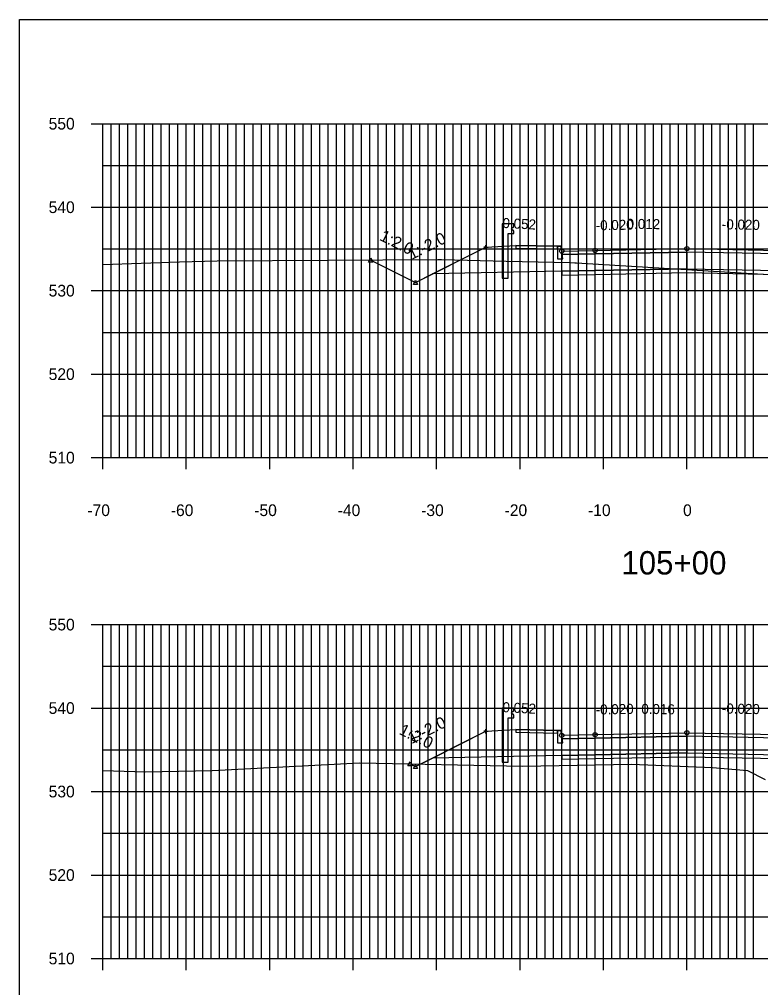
# Model space of a CAD drawing. Extents: x 1509063 to 1512863, y 401160 to 402918.
# Drawn here: x 1511822.7 to 1511911.6, y 402346.1 to 402462.1 of the extents above; entities that cross this region are included whole.
import ezdxf

# ---------------------------------------------------------------- set-up
doc = ezdxf.new("R2010")
doc.units = 0
for name, color, linetype in [('DD_P', 7, 'Continuous'), ('LCUT_P', 7, 'Continuous'), ('NBL1', 7, 'Continuous'), ('PET_P', 7, 'Continuous'), ('PRC', 7, 'Continuous'), ('PSP_P', 7, 'Continuous'), ('RBS_P', 7, 'Continuous'), ('RCC_P', 7, 'Continuous'), ('RGR_P', 7, 'Continuous'), ('XAX_P', 7, 'Continuous'), ('XAXTIC_P', 7, 'Continuous'), ('XAXTXT_P_T', 7, 'Continuous'), ('XGL_P', 7, 'Continuous'), ('XSL1_P', 7, 'Continuous'), ('XSL1_P_T', 7, 'Continuous'), ('XSL2_P', 7, 'Continuous'), ('XSL3_P', 7, 'Continuous'), ('XSLOG', 7, 'Continuous')]:
    doc.layers.add(name, color=color, linetype=linetype)

msp = doc.modelspace()

# ---------------------------------------------------------------- linework, layer by layer
at = {"layer": 'DD_P'}
for points in [[(1511864.84, 402433.25), (1511870.2, 402430.57), (1511878.65, 402434.8), (1511882.23, 402435.01)], [(1511869.55, 402372.9), (1511870.2, 402372.57), (1511878.65, 402376.8), (1511882.23, 402377.01)]]:
    msp.add_lwpolyline(points, dxfattribs=at)
for points in [[(1511870.2, 402430.82), (1511870.45, 402430.32), (1511869.95, 402430.32)], [(1511870.2, 402372.82), (1511870.45, 402372.32), (1511869.95, 402372.32)]]:
    msp.add_lwpolyline(points, close=True, dxfattribs=at)
at = {"layer": 'LCUT_P'}
for points in [[(1511864.84, 402433.5), (1511865.09, 402433), (1511864.59, 402433)], [(1511869.55, 402373.15), (1511869.8, 402372.65), (1511869.3, 402372.65)]]:
    msp.add_lwpolyline(points, close=True, dxfattribs=at)
at = {"layer": 'NBL1'}
msp.add_lwpolyline([(1512142.73, 402252.08), (1511822.73, 402252.08), (1511822.73, 402462.08), (1512142.73, 402462.08)], close=True, dxfattribs=at)
at = {"layer": 'PET_P'}
for centre in [(1511891.73, 402434.4), (1511891.73, 402376.4)]:
    msp.add_circle(centre, 0.25, dxfattribs=at)
at = {"layer": 'PRC'}
for centre in [(1511902.73, 402434.62), (1511902.73, 402376.62)]:
    msp.add_circle(centre, 0.25, dxfattribs=at)
at = {"layer": 'PSP_P'}
for centre in [(1511887.73, 402434.32), (1511887.73, 402376.32)]:
    msp.add_circle(centre, 0.25, dxfattribs=at)
at = {"layer": 'RBS_P'}
for points in [[(1511887.8, 402433.9), (1511891.73, 402433.98), (1511902.73, 402434.2), (1511902.73, 402432.2), (1511891.73, 402431.98), (1511887.8, 402431.9), (1511872.24, 402431.59), (1511878.65, 402434.8), (1511882.23, 402435.01), (1511882.23, 402434.68), (1511887.23, 402434.58), (1511887.23, 402433.41), (1511887.88, 402433.41)], [(1511902.73, 402434.2), (1511902.73, 402432.2), (1511913.73, 402431.98), (1511917.73, 402431.9), (1511928.24, 402431.69), (1511917.73, 402434.32), (1511917.73, 402433.9), (1511913.73, 402433.98)], [(1511887.8, 402375.9), (1511891.73, 402375.98), (1511902.73, 402376.2), (1511902.73, 402374.2), (1511891.73, 402373.98), (1511887.8, 402373.9), (1511872.24, 402373.59), (1511878.65, 402376.8), (1511882.23, 402377.01), (1511882.23, 402376.68), (1511887.23, 402376.58), (1511887.23, 402375.41), (1511887.88, 402375.41)], [(1511902.73, 402376.2), (1511902.73, 402374.2), (1511913.73, 402373.98), (1511917.73, 402373.9), (1511928.57, 402373.69), (1511921.31, 402376.1), (1511917.73, 402376.32), (1511917.73, 402375.9), (1511913.73, 402375.98)]]:
    msp.add_lwpolyline(points, close=True, dxfattribs=at)
for points in [[(1511878.65, 402434.8), (1511878.65, 402435.05), (1511878.65, 402434.8), (1511878.4, 402434.8), (1511878.65, 402434.8), (1511878.65, 402434.55), (1511878.65, 402434.8), (1511878.9, 402434.8)], [(1511878.65, 402376.8), (1511878.65, 402377.05), (1511878.65, 402376.8), (1511878.4, 402376.8), (1511878.65, 402376.8), (1511878.65, 402376.55), (1511878.65, 402376.8), (1511878.9, 402376.8)]]:
    msp.add_lwpolyline(points, dxfattribs=at)
at = {"layer": 'RCC_P'}
for points in [[(1511887.73, 402434.32), (1511887.63, 402434.9), (1511887.23, 402434.91), (1511887.23, 402433.41), (1511887.88, 402433.41)], [(1511887.73, 402376.32), (1511887.63, 402376.9), (1511887.23, 402376.91), (1511887.23, 402375.41), (1511887.88, 402375.41)]]:
    msp.add_lwpolyline(points, close=True, dxfattribs=at)
at = {"layer": 'RGR_P'}
for points in [[(1511881.29, 402436.41), (1511881.98, 402436.41), (1511881.98, 402436.71), (1511881.68, 402436.99), (1511881.98, 402437.28), (1511881.98, 402437.58), (1511880.6, 402437.58), (1511880.6, 402431.08), (1511881.29, 402431.08)], [(1511881.29, 402378.41), (1511881.98, 402378.41), (1511881.98, 402378.71), (1511881.68, 402378.99), (1511881.98, 402379.28), (1511881.98, 402379.58), (1511880.6, 402379.58), (1511880.6, 402373.08), (1511881.29, 402373.08)]]:
    msp.add_lwpolyline(points, close=True, dxfattribs=at)
at = {"layer": 'XAX_P'}
for p, q in [((1511832.73, 402409.58), (1511832.73, 402449.58)), ((1511902.73, 402409.58), (1511902.73, 402449.58)), ((1511832.73, 402409.58), (1511972.73, 402409.58)), ((1511832.73, 402349.58), (1511832.73, 402389.58)), ((1511902.73, 402349.58), (1511902.73, 402389.58)), ((1511832.73, 402349.58), (1511972.73, 402349.58))]:
    msp.add_line(p, q, dxfattribs=at)
at = {"layer": 'XAXTIC_P'}
for p, q in [((1511831.33, 402449.58), (1511834.13, 402449.58)), ((1511901.33, 402449.58), (1511904.13, 402449.58)), ((1511831.33, 402439.58), (1511834.13, 402439.58)), ((1511901.33, 402439.58), (1511904.13, 402439.58)), ((1511831.33, 402429.58), (1511834.13, 402429.58)), ((1511901.33, 402429.58), (1511904.13, 402429.58)), ((1511831.33, 402419.58), (1511834.13, 402419.58)), ((1511901.33, 402419.58), (1511904.13, 402419.58)), ((1511832.73, 402408.18), (1511832.73, 402410.98)), ((1511842.73, 402408.18), (1511842.73, 402410.98)), ((1511852.73, 402408.18), (1511852.73, 402410.98)), ((1511862.73, 402408.18), (1511862.73, 402410.98)), ((1511872.73, 402408.18), (1511872.73, 402410.98)), ((1511882.73, 402408.18), (1511882.73, 402410.98)), ((1511892.73, 402408.18), (1511892.73, 402410.98)), ((1511902.73, 402408.18), (1511902.73, 402410.98)), ((1511831.33, 402409.58), (1511834.13, 402409.58)), ((1511901.33, 402409.58), (1511904.13, 402409.58)), ((1511831.33, 402389.58), (1511834.13, 402389.58)), ((1511901.33, 402389.58), (1511904.13, 402389.58)), ((1511831.33, 402379.58), (1511834.13, 402379.58)), ((1511901.33, 402379.58), (1511904.13, 402379.58)), ((1511831.33, 402369.58), (1511834.13, 402369.58)), ((1511901.33, 402369.58), (1511904.13, 402369.58)), ((1511831.33, 402359.58), (1511834.13, 402359.58)), ((1511901.33, 402359.58), (1511904.13, 402359.58)), ((1511832.73, 402348.18), (1511832.73, 402350.98)), ((1511842.73, 402348.18), (1511842.73, 402350.98)), ((1511852.73, 402348.18), (1511852.73, 402350.98)), ((1511862.73, 402348.18), (1511862.73, 402350.98)), ((1511872.73, 402348.18), (1511872.73, 402350.98)), ((1511882.73, 402348.18), (1511882.73, 402350.98)), ((1511892.73, 402348.18), (1511892.73, 402350.98)), ((1511902.73, 402348.18), (1511902.73, 402350.98)), ((1511831.33, 402349.58), (1511834.13, 402349.58)), ((1511901.33, 402349.58), (1511904.13, 402349.58))]:
    msp.add_line(p, q, dxfattribs=at)
at = {"layer": 'XGL_P'}
for p, q in [((1511832.73, 402449.58), (1511972.73, 402449.58)), ((1511832.73, 402409.58), (1511832.73, 402449.58)), ((1511833.73, 402409.58), (1511833.73, 402449.58)), ((1511834.73, 402409.58), (1511834.73, 402449.58)), ((1511835.73, 402409.58), (1511835.73, 402449.58)), ((1511836.73, 402409.58), (1511836.73, 402449.58)), ((1511837.73, 402409.58), (1511837.73, 402449.58)), ((1511838.73, 402409.58), (1511838.73, 402449.58)), ((1511839.73, 402409.58), (1511839.73, 402449.58)), ((1511840.73, 402409.58), (1511840.73, 402449.58)), ((1511841.73, 402409.58), (1511841.73, 402449.58)), ((1511842.73, 402409.58), (1511842.73, 402449.58)), ((1511843.73, 402409.58), (1511843.73, 402449.58)), ((1511844.73, 402409.58), (1511844.73, 402449.58)), ((1511845.73, 402409.58), (1511845.73, 402449.58)), ((1511846.73, 402409.58), (1511846.73, 402449.58)), ((1511847.73, 402409.58), (1511847.73, 402449.58)), ((1511848.73, 402409.58), (1511848.73, 402449.58)), ((1511849.73, 402409.58), (1511849.73, 402449.58)), ((1511850.73, 402409.58), (1511850.73, 402449.58)), ((1511851.73, 402409.58), (1511851.73, 402449.58)), ((1511852.73, 402409.58), (1511852.73, 402449.58)), ((1511853.73, 402409.58), (1511853.73, 402449.58)), ((1511854.73, 402409.58), (1511854.73, 402449.58)), ((1511855.73, 402409.58), (1511855.73, 402449.58)), ((1511856.73, 402409.58), (1511856.73, 402449.58)), ((1511857.73, 402409.58), (1511857.73, 402449.58)), ((1511858.73, 402409.58), (1511858.73, 402449.58)), ((1511859.73, 402409.58), (1511859.73, 402449.58)), ((1511860.73, 402409.58), (1511860.73, 402449.58)), ((1511861.73, 402409.58), (1511861.73, 402449.58)), ((1511862.73, 402409.58), (1511862.73, 402449.58)), ((1511863.73, 402409.58), (1511863.73, 402449.58)), ((1511864.73, 402409.58), (1511864.73, 402449.58)), ((1511865.73, 402409.58), (1511865.73, 402449.58)), ((1511866.73, 402409.58), (1511866.73, 402449.58)), ((1511867.73, 402409.58), (1511867.73, 402449.58)), ((1511868.73, 402409.58), (1511868.73, 402449.58)), ((1511869.73, 402409.58), (1511869.73, 402449.58)), ((1511870.73, 402409.58), (1511870.73, 402449.58)), ((1511871.73, 402409.58), (1511871.73, 402449.58)), ((1511872.73, 402409.58), (1511872.73, 402449.58)), ((1511873.73, 402409.58), (1511873.73, 402449.58)), ((1511874.73, 402409.58), (1511874.73, 402449.58)), ((1511875.73, 402409.58), (1511875.73, 402449.58)), ((1511876.73, 402409.58), (1511876.73, 402449.58)), ((1511877.73, 402409.58), (1511877.73, 402449.58)), ((1511878.73, 402409.58), (1511878.73, 402449.58)), ((1511879.73, 402409.58), (1511879.73, 402449.58)), ((1511880.73, 402409.58), (1511880.73, 402449.58)), ((1511881.73, 402409.58), (1511881.73, 402449.58)), ((1511882.73, 402409.58), (1511882.73, 402449.58)), ((1511883.73, 402409.58), (1511883.73, 402449.58)), ((1511884.73, 402409.58), (1511884.73, 402449.58)), ((1511885.73, 402409.58), (1511885.73, 402449.58)), ((1511886.73, 402409.58), (1511886.73, 402449.58)), ((1511887.73, 402409.58), (1511887.73, 402449.58)), ((1511888.73, 402409.58), (1511888.73, 402449.58)), ((1511889.73, 402409.58), (1511889.73, 402449.58)), ((1511890.73, 402409.58), (1511890.73, 402449.58)), ((1511891.73, 402409.58), (1511891.73, 402449.58)), ((1511892.73, 402409.58), (1511892.73, 402449.58)), ((1511893.73, 402409.58), (1511893.73, 402449.58)), ((1511894.73, 402409.58), (1511894.73, 402449.58)), ((1511895.73, 402409.58), (1511895.73, 402449.58)), ((1511896.73, 402409.58), (1511896.73, 402449.58)), ((1511897.73, 402409.58), (1511897.73, 402449.58)), ((1511898.73, 402409.58), (1511898.73, 402449.58)), ((1511899.73, 402409.58), (1511899.73, 402449.58)), ((1511900.73, 402409.58), (1511900.73, 402449.58)), ((1511901.73, 402409.58), (1511901.73, 402449.58)), ((1511902.73, 402409.58), (1511902.73, 402449.58)), ((1511903.73, 402409.58), (1511903.73, 402449.58)), ((1511904.73, 402409.58), (1511904.73, 402449.58)), ((1511905.73, 402409.58), (1511905.73, 402449.58)), ((1511906.73, 402409.58), (1511906.73, 402449.58)), ((1511907.73, 402409.58), (1511907.73, 402449.58)), ((1511908.73, 402409.58), (1511908.73, 402449.58)), ((1511909.73, 402409.58), (1511909.73, 402449.58)), ((1511910.73, 402409.58), (1511910.73, 402449.58)), ((1511832.73, 402444.58), (1511972.73, 402444.58)), ((1511832.73, 402439.58), (1511972.73, 402439.58)), ((1511832.73, 402434.58), (1511972.73, 402434.58)), ((1511832.73, 402429.58), (1511972.73, 402429.58)), ((1511832.73, 402424.58), (1511972.73, 402424.58)), ((1511832.73, 402419.58), (1511972.73, 402419.58)), ((1511832.73, 402414.58), (1511972.73, 402414.58)), ((1511832.73, 402409.58), (1511972.73, 402409.58)), ((1511832.73, 402389.58), (1511972.73, 402389.58)), ((1511832.73, 402349.58), (1511832.73, 402389.58)), ((1511833.73, 402349.58), (1511833.73, 402389.58)), ((1511834.73, 402349.58), (1511834.73, 402389.58)), ((1511835.73, 402349.58), (1511835.73, 402389.58)), ((1511836.73, 402349.58), (1511836.73, 402389.58)), ((1511837.73, 402349.58), (1511837.73, 402389.58)), ((1511838.73, 402349.58), (1511838.73, 402389.58)), ((1511839.73, 402349.58), (1511839.73, 402389.58)), ((1511840.73, 402349.58), (1511840.73, 402389.58)), ((1511841.73, 402349.58), (1511841.73, 402389.58)), ((1511842.73, 402349.58), (1511842.73, 402389.58)), ((1511843.73, 402349.58), (1511843.73, 402389.58)), ((1511844.73, 402349.58), (1511844.73, 402389.58)), ((1511845.73, 402349.58), (1511845.73, 402389.58)), ((1511846.73, 402349.58), (1511846.73, 402389.58)), ((1511847.73, 402349.58), (1511847.73, 402389.58)), ((1511848.73, 402349.58), (1511848.73, 402389.58)), ((1511849.73, 402349.58), (1511849.73, 402389.58)), ((1511850.73, 402349.58), (1511850.73, 402389.58)), ((1511851.73, 402349.58), (1511851.73, 402389.58)), ((1511852.73, 402349.58), (1511852.73, 402389.58)), ((1511853.73, 402349.58), (1511853.73, 402389.58)), ((1511854.73, 402349.58), (1511854.73, 402389.58)), ((1511855.73, 402349.58), (1511855.73, 402389.58)), ((1511856.73, 402349.58), (1511856.73, 402389.58)), ((1511857.73, 402349.58), (1511857.73, 402389.58)), ((1511858.73, 402349.58), (1511858.73, 402389.58)), ((1511859.73, 402349.58), (1511859.73, 402389.58)), ((1511860.73, 402349.58), (1511860.73, 402389.58)), ((1511861.73, 402349.58), (1511861.73, 402389.58)), ((1511862.73, 402349.58), (1511862.73, 402389.58)), ((1511863.73, 402349.58), (1511863.73, 402389.58)), ((1511864.73, 402349.58), (1511864.73, 402389.58)), ((1511865.73, 402349.58), (1511865.73, 402389.58)), ((1511866.73, 402349.58), (1511866.73, 402389.58)), ((1511867.73, 402349.58), (1511867.73, 402389.58)), ((1511868.73, 402349.58), (1511868.73, 402389.58)), ((1511869.73, 402349.58), (1511869.73, 402389.58)), ((1511870.73, 402349.58), (1511870.73, 402389.58)), ((1511871.73, 402349.58), (1511871.73, 402389.58)), ((1511872.73, 402349.58), (1511872.73, 402389.58)), ((1511873.73, 402349.58), (1511873.73, 402389.58)), ((1511874.73, 402349.58), (1511874.73, 402389.58)), ((1511875.73, 402349.58), (1511875.73, 402389.58)), ((1511876.73, 402349.58), (1511876.73, 402389.58)), ((1511877.73, 402349.58), (1511877.73, 402389.58)), ((1511878.73, 402349.58), (1511878.73, 402389.58)), ((1511879.73, 402349.58), (1511879.73, 402389.58)), ((1511880.73, 402349.58), (1511880.73, 402389.58)), ((1511881.73, 402349.58), (1511881.73, 402389.58)), ((1511882.73, 402349.58), (1511882.73, 402389.58)), ((1511883.73, 402349.58), (1511883.73, 402389.58)), ((1511884.73, 402349.58), (1511884.73, 402389.58)), ((1511885.73, 402349.58), (1511885.73, 402389.58)), ((1511886.73, 402349.58), (1511886.73, 402389.58)), ((1511887.73, 402349.58), (1511887.73, 402389.58)), ((1511888.73, 402349.58), (1511888.73, 402389.58)), ((1511889.73, 402349.58), (1511889.73, 402389.58)), ((1511890.73, 402349.58), (1511890.73, 402389.58)), ((1511891.73, 402349.58), (1511891.73, 402389.58)), ((1511892.73, 402349.58), (1511892.73, 402389.58)), ((1511893.73, 402349.58), (1511893.73, 402389.58)), ((1511894.73, 402349.58), (1511894.73, 402389.58)), ((1511895.73, 402349.58), (1511895.73, 402389.58)), ((1511896.73, 402349.58), (1511896.73, 402389.58)), ((1511897.73, 402349.58), (1511897.73, 402389.58)), ((1511898.73, 402349.58), (1511898.73, 402389.58)), ((1511899.73, 402349.58), (1511899.73, 402389.58)), ((1511900.73, 402349.58), (1511900.73, 402389.58)), ((1511901.73, 402349.58), (1511901.73, 402389.58)), ((1511902.73, 402349.58), (1511902.73, 402389.58)), ((1511903.73, 402349.58), (1511903.73, 402389.58)), ((1511904.73, 402349.58), (1511904.73, 402389.58)), ((1511905.73, 402349.58), (1511905.73, 402389.58)), ((1511906.73, 402349.58), (1511906.73, 402389.58)), ((1511907.73, 402349.58), (1511907.73, 402389.58)), ((1511908.73, 402349.58), (1511908.73, 402389.58)), ((1511909.73, 402349.58), (1511909.73, 402389.58)), ((1511910.73, 402349.58), (1511910.73, 402389.58)), ((1511832.73, 402384.58), (1511972.73, 402384.58)), ((1511832.73, 402379.58), (1511972.73, 402379.58)), ((1511832.73, 402374.58), (1511972.73, 402374.58)), ((1511832.73, 402369.58), (1511972.73, 402369.58)), ((1511832.73, 402364.58), (1511972.73, 402364.58)), ((1511832.73, 402359.58), (1511972.73, 402359.58)), ((1511832.73, 402354.58), (1511972.73, 402354.58)), ((1511832.73, 402349.58), (1511972.73, 402349.58))]:
    msp.add_line(p, q, dxfattribs=at)
at = {"layer": 'XSL1_P'}
for points in [[(1511864.84, 402433.25), (1511870.2, 402430.57), (1511872.24, 402431.59), (1511878.65, 402434.8), (1511882.23, 402435.01), (1511887.23, 402434.91), (1511887.63, 402434.9), (1511887.73, 402434.32), (1511891.73, 402434.4), (1511902.73, 402434.62), (1511913.73, 402434.4), (1511917.73, 402434.32), (1511928.24, 402431.69), (1511930.41, 402431.15), (1511938.09, 402429.23)], [(1511869.55, 402372.9), (1511870.2, 402372.57), (1511872.24, 402373.59), (1511878.65, 402376.8), (1511882.23, 402377.01), (1511887.23, 402376.91), (1511887.63, 402376.9), (1511887.73, 402376.32), (1511891.73, 402376.4), (1511902.73, 402376.62), (1511913.73, 402376.4), (1511917.73, 402376.32), (1511921.31, 402376.1), (1511928.56, 402373.69), (1511930.16, 402373.15), (1511937.67, 402370.65), (1511970.85, 402368.05)]]:
    msp.add_lwpolyline(points, dxfattribs=at)
for points in [[(1511887.23, 402434.91), (1511882.23, 402435.01), (1511882.23, 402434.68), (1511887.23, 402434.58)], [(1511887.23, 402376.91), (1511882.23, 402377.01), (1511882.23, 402376.68), (1511887.23, 402376.58)]]:
    msp.add_lwpolyline(points, close=True, dxfattribs=at)
at = {"layer": 'XSL2_P'}
for points in [[(1511887.8, 402431.9), (1511872.24, 402431.59)], [(1511887.8, 402373.9), (1511872.24, 402373.59)]]:
    msp.add_lwpolyline(points, dxfattribs=at)
for points in [[(1511913.73, 402431.48), (1511902.73, 402431.7), (1511891.73, 402431.48), (1511887.8, 402431.4), (1511887.8, 402431.9), (1511891.73, 402431.98), (1511902.73, 402432.2), (1511913.73, 402431.98), (1511917.73, 402431.9), (1511917.73, 402431.4)], [(1511913.73, 402373.48), (1511902.73, 402373.7), (1511891.73, 402373.48), (1511887.8, 402373.4), (1511887.8, 402373.9), (1511891.73, 402373.98), (1511902.73, 402374.2), (1511913.73, 402373.98), (1511917.73, 402373.9), (1511917.73, 402373.4)]]:
    msp.add_lwpolyline(points, close=True, dxfattribs=at)
at = {"layer": 'XSL3_P'}
for points in [[(1511891.73, 402433.98), (1511887.8, 402433.9), (1511887.73, 402434.32), (1511891.73, 402434.4), (1511902.73, 402434.62), (1511913.73, 402434.4), (1511917.73, 402434.32), (1511917.73, 402433.9), (1511913.73, 402433.98), (1511902.73, 402434.2)], [(1511891.73, 402375.98), (1511887.8, 402375.9), (1511887.73, 402376.32), (1511891.73, 402376.4), (1511902.73, 402376.62), (1511913.73, 402376.4), (1511917.73, 402376.32), (1511917.73, 402375.9), (1511913.73, 402375.98), (1511902.73, 402376.2)]]:
    msp.add_lwpolyline(points, close=True, dxfattribs=at)
at = {"layer": 'XSLOG'}
for points in [[(1511832.73, 402432.73), (1511841.93, 402433.03), (1511846.44, 402433.14), (1511872.86, 402433.3), (1511873.33, 402433.3), (1511881.07, 402433.12), (1511888.73, 402432.96), (1511889.29, 402432.92), (1511889.51, 402432.91), (1511913.83, 402431.43)], [(1511832.73, 402372.11), (1511837.85, 402371.94), (1511845.82, 402372.12), (1511863.54, 402373.03), (1511883.07, 402372.61), (1511896.07, 402372.86), (1511905.79, 402372.46), (1511909.99, 402372.09), (1511912.09, 402371.01)]]:
    msp.add_lwpolyline(points, dxfattribs=at)

# ---------------------------------------------------------------- texts
at = {"layer": 'XAXTXT_P_T'}
for s, height, p in [('550', 1.4, (1511826.24, 402448.88)), ('540', 1.4, (1511826.24, 402438.88)), ('530', 1.4, (1511826.24, 402428.88)), ('520', 1.4, (1511826.24, 402418.88)), ('510', 1.4, (1511826.24, 402408.88)), ('-70', 1.4, (1511830.88, 402402.58)), ('-60', 1.4, (1511840.88, 402402.58)), ('-50', 1.4, (1511850.88, 402402.58)), ('-40', 1.4, (1511860.88, 402402.58)), ('-30', 1.4, (1511870.88, 402402.58)), ('-20', 1.4, (1511880.88, 402402.58)), ('-10', 1.4, (1511890.88, 402402.58)), ('0', 1.4, (1511902.27, 402402.58)), ('105+00', 2.8, (1511894.87, 402395.58)), ('550', 1.4, (1511826.24, 402388.88)), ('540', 1.4, (1511826.24, 402378.88)), ('530', 1.4, (1511826.24, 402368.88)), ('520', 1.4, (1511826.24, 402358.88)), ('510', 1.4, (1511826.24, 402348.88))]:
    msp.add_text(s, height=height, dxfattribs=at).set_placement(p)
at = {"layer": 'XSL1_P_T'}
for s, height, rotation, p in [('0.052', 1.2, 356.9978, (1511880.6, 402437.1)), ('-0.020', 1.2, 1.1458, (1511891.81, 402436.8)), ('0.012', 1.2, 359.3017, (1511895.5, 402436.99)), ('0.012', 1.2, 359.3017, (1511895.5, 402436.99)), ('-0.020', 1.2, 358.8542, (1511906.91, 402436.94)), ('1:2.0', 1.4, 333.4349, (1511865.79, 402435.68)), ('1:2.0', 1.4, 333.4349, (1511865.79, 402435.68)), ('1:2.0', 1.4, 333.4349, (1511865.79, 402435.68)), ('1:-2.0', 1.4, 26.5651, (1511869.74, 402433.25)), ('1:-2.0', 1.4, 26.5651, (1511869.74, 402433.25)), ('1:-2.0', 1.4, 26.5651, (1511869.74, 402433.25)), ('0.052', 1.2, 356.9978, (1511880.6, 402379.1)), ('-0.020', 1.2, 1.1458, (1511891.81, 402378.8)), ('0.016', 1.2, 359.0718, (1511897.26, 402378.89)), ('0.016', 1.2, 359.0718, (1511897.26, 402378.89)), ('-0.020', 1.2, 358.8542, (1511906.91, 402378.94)), ('1:-2.0', 1.4, 26.5651, (1511869.74, 402375.25)), ('1:-2.0', 1.4, 26.5651, (1511869.74, 402375.25)), ('1:-2.0', 1.4, 26.5651, (1511869.74, 402375.25)), ('1:2.0', 1.4, 333.4349, (1511868.14, 402376.51)), ('1:2.0', 1.4, 333.4349, (1511868.14, 402376.51)), ('1:2.0', 1.4, 333.4349, (1511868.14, 402376.51))]:
    msp.add_text(s, height=height, rotation=rotation, dxfattribs=at).set_placement(p)

doc.saveas('drawing.dxf')
